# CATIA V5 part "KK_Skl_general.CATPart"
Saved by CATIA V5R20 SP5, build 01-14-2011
Part number: Skl_général
Property "Longueur.arbre_manche": 100 mm
Property "Longueur.maneton": 15 mm
Property "Longueur.biellette": 50 mm
Property "Longueur.lame_scie": 200 mm
Publications: "Plan_Ref1", "Point.1", "Point.2", "Point.3", "Plan.Ref2", "Plan.Ref3", "Point.4", "Point.5", "Point.6", "Point.7", "Point.8", "Plan.Ref4", "Plan.Ref5", "Point.9", "Point.10", "Point.11", "Point.12", "Point.13", "Point.14", "Plan.6", "Plan.7", "Plan.8", "Plan.9", "Plan.Ref6"
Bounding box of the stored display mesh (mm): x 0 to 12.5, y 0 to 335, z -15 to 15
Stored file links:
  G:\Khaled_CFAO_2011\ST2M\ST2M_GR2\aandujar\Khaled\CAD_thinkMOTION\KK_Skl_general.CATPart
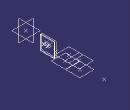
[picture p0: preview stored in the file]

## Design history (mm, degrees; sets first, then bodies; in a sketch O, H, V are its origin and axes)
Set1
  Plane1 "Plan_Ref1": type Offset, RefPlane yz-plane, Offset 0
  Point1: (0, 0, 0)
  Point2: (0, 100, 0)
  Point3: (5, 100, 0)
  Plane2 "Plan.Ref2": type OffsetPt, RefPlane Plane1, RefPoint Point3
  Plane3 "Plan.Ref3": type Offset, RefPlane Plane2, Offset 5
  Point4: type OnPlane, Support Plane3, H 100, V 0, Direction (0, 1, 0)
  Point5: type OnPlane, Support Plane3, RefPoint Point4, H -15, V 0, Direction (0, 1, 0)
  Point6: type OnPlane, Support Plane5, RefPoint Point4, H 35, V 0, Direction (0, 1, 0)
  Point7: type OnPlane, Support Plane5, RefPoint Point6, H 200, V 0, Direction (0, 1, 0)
  Point8: type OnPlane, Support Plane1, H 85, V 0, Direction (0, 1, 0)
  Plane4 "Plan.Ref4": type Offset, RefPlane xy-plane, Offset 0
  Plane5 "Plan.Ref5": type Offset, RefPlane Plane3, Offset 2.5
  Point9: type OnPlane, Support Plane5, H 100, V 0, Direction (0, 1, 0)
  Point10: type OnPlane, Support Plane5, RefPoint Point9, H -15, V 0, Direction (0, 1, 0)
  Point11: type OnPlane, Support Plane5, RefPoint Point6, H 40, V -15, Direction (0, 1, 0)
  Point12: type OnPlane, Support Plane5, RefPoint Point6, H 100, V -15, Direction (0, 1, 0)
  Point13: type OnPlane, Support Plane5, RefPoint Point6, H 55, V 15, Direction (0, 1, 0)
  Point14: type OnPlane, Support Plane5, RefPoint Point6, H 97, V 15, Direction (0, 1, 0)
  Plane6: type OffsetPt, RefPlane Plane4, RefPoint Point12
  Plane7: type OffsetPt, RefPlane Plane4, RefPoint Point11
  Plane8: type OffsetPt, RefPlane Plane4, RefPoint Point13
  Plane9: type OffsetPt, RefPlane Plane4, RefPoint Point14
  Plane10 "Plan.Ref6": type Offset, RefPlane zx-plane, Offset 0
Body1 (main body)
